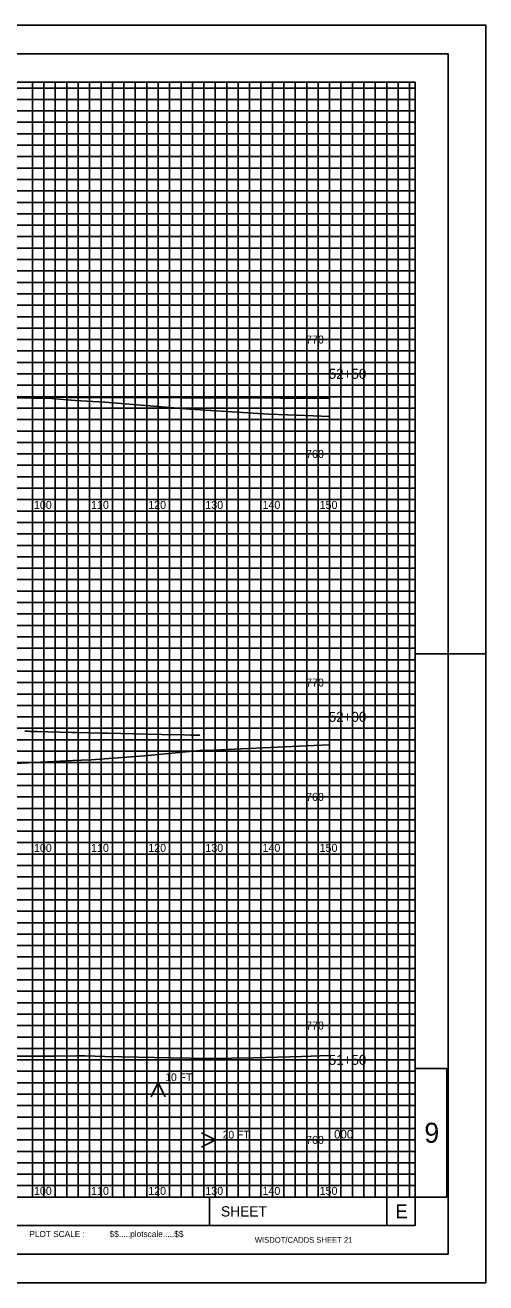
# Model space of a CAD drawing. Extents: x 578243 to 601557, y 174899 to 175559.
# Drawn here: x 601476.6 to 601557.2, y 175338.8 to 175558.8 of the extents above; entities that cross this region are included whole.
import ezdxf

# ---------------------------------------------------------------- set-up
doc = ezdxf.new("R2010")
doc.units = 0
for name, color, linetype in [('E_PROF_Grid', 7, 'Continuous'), ('E_PROF_GridMin', 7, 'Continuous'), ('P_E_XS_Ground', 7, 'Continuous'), ('P_SURF_Final_Top', 7, 'Continuous'), ('P_XS_Text', 7, 'Continuous'), ('PLT_Sheet_Border', 7, 'Continuous'), ('PLT_Sheet_Info', 7, 'Continuous')]:
    doc.layers.add(name, color=color, linetype=linetype)

msp = doc.modelspace()

# ---------------------------------------------------------------- linework, layer by layer
at = {"layer": 'E_PROF_Grid'}
for p, q in [((601479.84, 175353.8), (601479.84, 175548.8)), ((601489.84, 175353.8), (601489.84, 175548.8)), ((601499.84, 175353.8), (601499.84, 175548.8)), ((601509.84, 175353.8), (601509.84, 175548.8)), ((601519.84, 175353.8), (601519.84, 175548.8)), ((601529.84, 175353.8), (601529.84, 175548.8)), ((601539.84, 175353.8), (601539.84, 175548.8)), ((601229.84, 175543.8), (601544.84, 175543.8)), ((601229.84, 175533.8), (601544.84, 175533.8)), ((601229.84, 175523.8), (601544.84, 175523.8)), ((601229.84, 175513.8), (601544.84, 175513.8)), ((601229.84, 175503.8), (601544.84, 175503.8)), ((601229.84, 175493.8), (601544.84, 175493.8)), ((601229.84, 175483.8), (601544.84, 175483.8)), ((601229.84, 175473.8), (601544.84, 175473.8)), ((601229.84, 175463.8), (601544.84, 175463.8)), ((601229.84, 175453.8), (601544.84, 175453.8)), ((601229.84, 175443.8), (601544.84, 175443.8)), ((601229.84, 175433.8), (601544.84, 175433.8)), ((601229.84, 175423.8), (601544.84, 175423.8)), ((601229.84, 175413.8), (601544.84, 175413.8)), ((601229.84, 175403.8), (601544.84, 175403.8)), ((601229.84, 175393.8), (601544.84, 175393.8)), ((601229.84, 175383.8), (601544.84, 175383.8)), ((601229.84, 175373.8), (601544.84, 175373.8)), ((601229.84, 175363.8), (601544.84, 175363.8))]:
    msp.add_line(p, q, dxfattribs=at)
at = {"layer": 'E_PROF_GridMin'}
for p, q in [((601229.84, 175547.8), (601544.84, 175547.8)), ((601477.84, 175353.8), (601477.84, 175548.8)), ((601481.84, 175353.8), (601481.84, 175548.8)), ((601483.84, 175353.8), (601483.84, 175548.8)), ((601485.84, 175353.8), (601485.84, 175548.8)), ((601487.84, 175353.8), (601487.84, 175548.8)), ((601491.84, 175353.8), (601491.84, 175548.8)), ((601493.84, 175353.8), (601493.84, 175548.8)), ((601495.84, 175353.8), (601495.84, 175548.8)), ((601497.84, 175353.8), (601497.84, 175548.8)), ((601501.84, 175353.8), (601501.84, 175548.8)), ((601503.84, 175353.8), (601503.84, 175548.8)), ((601505.84, 175353.8), (601505.84, 175548.8)), ((601507.84, 175353.8), (601507.84, 175548.8)), ((601511.84, 175353.8), (601511.84, 175548.8)), ((601513.84, 175353.8), (601513.84, 175548.8)), ((601515.84, 175353.8), (601515.84, 175548.8)), ((601517.84, 175353.8), (601517.84, 175548.8)), ((601521.84, 175353.8), (601521.84, 175548.8)), ((601523.84, 175353.8), (601523.84, 175548.8)), ((601525.84, 175353.8), (601525.84, 175548.8)), ((601527.84, 175353.8), (601527.84, 175548.8)), ((601531.84, 175353.8), (601531.84, 175548.8)), ((601533.84, 175353.8), (601533.84, 175548.8)), ((601535.84, 175353.8), (601535.84, 175548.8)), ((601537.84, 175353.8), (601537.84, 175548.8)), ((601541.84, 175353.8), (601541.84, 175548.8)), ((601543.84, 175353.8), (601543.84, 175548.8)), ((601229.84, 175545.8), (601544.84, 175545.8)), ((601229.84, 175541.8), (601544.84, 175541.8)), ((601229.84, 175539.8), (601544.84, 175539.8)), ((601229.84, 175537.8), (601544.84, 175537.8)), ((601229.84, 175535.8), (601544.84, 175535.8)), ((601229.84, 175531.8), (601544.84, 175531.8)), ((601229.84, 175529.8), (601544.84, 175529.8)), ((601229.84, 175527.8), (601544.84, 175527.8)), ((601229.84, 175525.8), (601544.84, 175525.8)), ((601229.84, 175521.8), (601544.84, 175521.8)), ((601229.84, 175519.8), (601544.84, 175519.8)), ((601229.84, 175517.8), (601544.84, 175517.8)), ((601229.84, 175515.8), (601544.84, 175515.8)), ((601229.84, 175511.8), (601544.84, 175511.8)), ((601229.84, 175509.8), (601544.84, 175509.8)), ((601229.84, 175507.8), (601544.84, 175507.8)), ((601229.84, 175505.8), (601544.84, 175505.8)), ((601229.84, 175501.8), (601544.84, 175501.8)), ((601229.84, 175499.8), (601544.84, 175499.8)), ((601229.84, 175497.8), (601544.84, 175497.8)), ((601229.84, 175495.8), (601544.84, 175495.8)), ((601229.84, 175491.8), (601544.84, 175491.8)), ((601229.84, 175489.8), (601544.84, 175489.8)), ((601229.84, 175487.8), (601544.84, 175487.8)), ((601229.84, 175485.8), (601544.84, 175485.8)), ((601229.84, 175481.8), (601544.84, 175481.8)), ((601229.84, 175479.8), (601544.84, 175479.8)), ((601229.84, 175477.8), (601544.84, 175477.8)), ((601229.84, 175475.8), (601544.84, 175475.8)), ((601229.84, 175471.8), (601544.84, 175471.8)), ((601229.84, 175469.8), (601544.84, 175469.8)), ((601229.84, 175467.8), (601544.84, 175467.8)), ((601229.84, 175465.8), (601544.84, 175465.8)), ((601229.84, 175461.8), (601544.84, 175461.8)), ((601229.84, 175459.8), (601544.84, 175459.8)), ((601229.84, 175457.8), (601544.84, 175457.8)), ((601229.84, 175455.8), (601544.84, 175455.8)), ((601229.84, 175451.8), (601544.84, 175451.8)), ((601229.84, 175449.8), (601544.84, 175449.8)), ((601229.84, 175447.8), (601544.84, 175447.8)), ((601229.84, 175445.8), (601544.84, 175445.8)), ((601229.84, 175441.8), (601544.84, 175441.8)), ((601229.84, 175439.8), (601544.84, 175439.8)), ((601229.84, 175437.8), (601544.84, 175437.8)), ((601229.84, 175435.8), (601544.84, 175435.8)), ((601229.84, 175431.8), (601544.84, 175431.8)), ((601229.84, 175429.8), (601544.84, 175429.8)), ((601229.84, 175427.8), (601544.84, 175427.8)), ((601229.84, 175425.8), (601544.84, 175425.8)), ((601229.84, 175421.8), (601544.84, 175421.8)), ((601229.84, 175419.8), (601544.84, 175419.8)), ((601229.84, 175417.8), (601544.84, 175417.8)), ((601229.84, 175415.8), (601544.84, 175415.8)), ((601229.84, 175411.8), (601544.84, 175411.8)), ((601229.84, 175409.8), (601544.84, 175409.8)), ((601229.84, 175407.8), (601544.84, 175407.8)), ((601229.84, 175405.8), (601544.84, 175405.8)), ((601229.84, 175401.8), (601544.84, 175401.8)), ((601229.84, 175399.8), (601544.84, 175399.8)), ((601229.84, 175397.8), (601544.84, 175397.8)), ((601229.84, 175395.8), (601544.84, 175395.8)), ((601229.84, 175391.8), (601544.84, 175391.8)), ((601229.84, 175389.8), (601544.84, 175389.8)), ((601229.84, 175387.8), (601544.84, 175387.8)), ((601229.84, 175385.8), (601544.84, 175385.8)), ((601229.84, 175381.8), (601544.84, 175381.8)), ((601229.84, 175379.8), (601544.84, 175379.8)), ((601229.84, 175377.8), (601544.84, 175377.8)), ((601229.84, 175375.8), (601544.84, 175375.8)), ((601229.84, 175371.8), (601544.84, 175371.8)), ((601229.84, 175369.8), (601544.84, 175369.8)), ((601229.84, 175367.8), (601544.84, 175367.8)), ((601229.84, 175365.8), (601544.84, 175365.8)), ((601229.84, 175361.8), (601544.84, 175361.8)), ((601229.84, 175359.8), (601544.84, 175359.8)), ((601229.84, 175357.8), (601544.84, 175357.8)), ((601229.84, 175355.8), (601544.84, 175355.8)), ((601557.19, 175338.8), (601557.19, 175348.8)), ((601547.19, 175338.8), (601557.19, 175338.8))]:
    msp.add_line(p, q, dxfattribs=at)
at = {"layer": 'P_E_XS_Ground'}
for points in [[(601467.93, 175493.73), (601481.24, 175493.49), (601485.34, 175493.15), (601490.5, 175492.83), (601505.37, 175491.64), (601519.21, 175490.74), (601524.09, 175490.57), (601529.84, 175490.37)], [(601471.39, 175429.44), (601484.94, 175430.15), (601486.41, 175430.24), (601488.13, 175430.26), (601497.43, 175430.98), (601507.16, 175431.91), (601509.58, 175431.99), (601514.37, 175432.21), (601527.06, 175432.78), (601529.84, 175432.9)], [(601472.83, 175378.42), (601481.97, 175378.43), (601485.54, 175378.52), (601486.99, 175378.51), (601490.53, 175378.41), (601502.14, 175378.14), (601508.84, 175378.04), (601516.51, 175378.17), (601524.96, 175378.41), (601529.84, 175378.55)]]:
    msp.add_lwpolyline(points, dxfattribs=at)
at = {"layer": 'P_SURF_Final_Top'}
for points in [[(601476.6, 175493.72), (601478.87, 175493.71), (601479.17, 175493.71), (601483.87, 175493.69), (601484.47, 175493.69), (601488.88, 175493.68), (601492.81, 175493.66), (601493.88, 175493.66), (601495.07, 175493.66), (601498.88, 175493.64), (601500.37, 175493.64), (601503.89, 175493.63), (601507.02, 175493.62), (601508.89, 175493.61), (601510.98, 175493.6), (601513.89, 175493.6), (601516.28, 175493.59), (601518.89, 175493.58), (601521.23, 175493.57), (601523.9, 175493.56), (601526.88, 175493.55), (601528.9, 175493.55), (601529.84, 175493.54)], [(601476.51, 175435.28), (601476.9, 175435.27), (601477.02, 175435.27), (601477.13, 175435.27), (601477.52, 175435.26), (601477.91, 175435.25), (601478.02, 175435.25), (601478.18, 175435.24), (601478.22, 175435.24), (601478.73, 175435.23), (601480.56, 175435.19), (601484.74, 175435.09), (601485.57, 175435.07), (601489.96, 175434.97), (601490.57, 175434.96), (601491.13, 175434.95), (601495.57, 175434.85), (601500.41, 175434.74), (601500.57, 175434.73), (601504.33, 175434.65), (601505.58, 175434.62), (601507.1, 175434.59), (601507.11, 175434.59), (601507.12, 175434.59), (601507.12, 175434.59)]]:
    msp.add_lwpolyline(points, dxfattribs=at)
at = {"layer": 'PLT_Sheet_Border'}
for points in [[(601217.19, 175338.8), (601557.19, 175338.8), (601557.19, 175558.8), (601217.19, 175558.8)], [(601219.59, 175343.8), (601550.59, 175343.8), (601550.59, 175553.8), (601219.59, 175553.8)]]:
    msp.add_lwpolyline(points, close=True, dxfattribs=at)
at = {"layer": 'PLT_Sheet_Info'}
for p, q in [((601547.19, 175558.8), (601557.19, 175558.8)), ((601557.19, 175548.8), (601557.19, 175558.8)), ((601229.84, 175548.8), (601544.84, 175548.8)), ((601544.84, 175348.8), (601544.84, 175548.8)), ((601557.19, 175443.8), (601557.19, 175453.8)), ((601557.19, 175448.8), (601544.84, 175448.8)), ((601229.84, 175353.8), (601544.84, 175353.8)), ((601508.84, 175348.8), (601508.84, 175353.8)), ((601539.84, 175348.8), (601539.84, 175353.8)), ((601229.84, 175348.8), (601544.84, 175348.8))]:
    msp.add_line(p, q, dxfattribs=at)
msp.add_lwpolyline([(601544.84, 175376.3), (601550.34, 175376.3), (601550.34, 175353.8), (601544.84, 175353.8)], close=True, dxfattribs=at)
for points in [[(601499.84, 175373.84), (601498.6, 175371.36)], [(601499.84, 175363.8), (601499.84, 175373.84), (601501.08, 175371.36)], [(601509.89, 175363.8), (601507.4, 175365.04)], [(601499.84, 175363.8), (601509.89, 175363.8), (601507.4, 175362.55)]]:
    msp.add_lwpolyline(points, dxfattribs=at)

# ---------------------------------------------------------------- texts
at = {"layer": 'P_XS_Text'}
for s, height, p in [('770', 1.4, (601525.72, 175503.1)), ('52+50', 1.75, (601529.7, 175496.93)), ('760', 1.4, (601525.72, 175483.1)), ('100', 1.4, (601478.1, 175474.18)), ('110', 1.4, (601488.1, 175474.18)), ('120', 1.4, (601498.1, 175474.18)), ('130', 1.4, (601508.1, 175474.18)), ('140', 1.4, (601518.1, 175474.18)), ('150', 1.4, (601528.1, 175474.18)), ('770', 1.4, (601525.72, 175443.1)), ('52+00', 1.75, (601529.7, 175436.93)), ('760', 1.4, (601525.72, 175423.1)), ('100', 1.4, (601478.1, 175414.18)), ('110', 1.4, (601488.1, 175414.18)), ('120', 1.4, (601498.1, 175414.18)), ('130', 1.4, (601508.1, 175414.18)), ('140', 1.4, (601518.1, 175414.18)), ('150', 1.4, (601528.1, 175414.18)), ('770', 1.4, (601525.72, 175383.1)), ('51+50', 1.75, (601529.7, 175376.93)), ('760', 1.4, (601525.72, 175363.1)), ('100', 1.4, (601478.1, 175354.19)), ('110', 1.4, (601488.1, 175354.19)), ('120', 1.4, (601498.1, 175354.19)), ('130', 1.4, (601508.1, 175354.19)), ('140', 1.4, (601518.1, 175354.19)), ('150', 1.4, (601528.1, 175354.19))]:
    msp.add_text(s, height=height, rotation=360, dxfattribs=at).set_placement(p)
at = {"layer": 'PLT_Sheet_Info'}
for s, height, p in [('  10 FT', 1.347, (601500.09, 175374.09)), ('9', 3.5, (601546.42, 175363.3)), ('  20 FT', 1.347, (601510.14, 175364.05)), ('     000', 1.5, (601527.84, 175364.05)), ('SHEET ', 1.8, (601510.84, 175350.4)), ('E', 2.4, (601541.36, 175350.11)), ('PLOT SCALE : ', 1.08, (601477.3, 175346.8)), ('$$.....plotscale.....$$', 1.08, (601491.34, 175346.8)), ('WISDOT/CADDS SHEET 21', 1, (601516.76, 175345.8))]:
    msp.add_text(s, height=height, dxfattribs=at).set_placement(p)

doc.saveas('drawing.dxf')
